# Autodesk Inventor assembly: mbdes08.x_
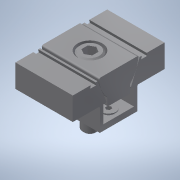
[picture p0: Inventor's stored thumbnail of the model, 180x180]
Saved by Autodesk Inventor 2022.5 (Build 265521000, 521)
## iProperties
Part Number: mbdes08.x_
Material: 一般
Document SubType Name: Assembly
Designer: ImaoCorp
Sending System: SOLIDWORKS 2017-2017317
MC: AMD64
MC_MODEL: Intel64 Family 6 Model 60 Stepping 3, GenuineIntel
OS: Windows_NT
FRU: Parasolid Version 29.0, build 201,  4-17-2017
FORMAT: text
GUISE: transmit
KEY: mbdes08
FILE: mbdes08.x_t
DATE: Fri Jul 26 11:35:17 2019
Author: ImaoCorp
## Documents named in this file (6)
- X:\14_SW2022-Inv2022\00_全2023-1023新製品(TCC)まで\m\mbdes08\MBDES08.iam
- X:\14_SW2022-Inv2022\00_全2023-1023新製品(TCC)まで\m\mbdes08\mbdes08_01.ipt
- X:\14_SW2022-Inv2022\00_全2023-1023新製品(TCC)まで\m\mbdes08\mbdes08_02.ipt
- X:\14_SW2022-Inv2022\00_全2023-1023新製品(TCC)まで\m\mbdes08\mbdes08_03.ipt
- X:\14_SW2022-Inv2022\00_全2023-1023新製品(TCC)まで\m\mbdes08\mbdes08_04.ipt
- X:\14_SW2022-Inv2022\00_全2023-1023新製品(TCC)まで\m\mbdes08\mbdes08_05.ipt
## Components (5 placed, 5 different names)
1. mbdes08_01
2. mbdes08_02
3. mbdes08_03
4. mbdes08_04
5. mbdes08_05
